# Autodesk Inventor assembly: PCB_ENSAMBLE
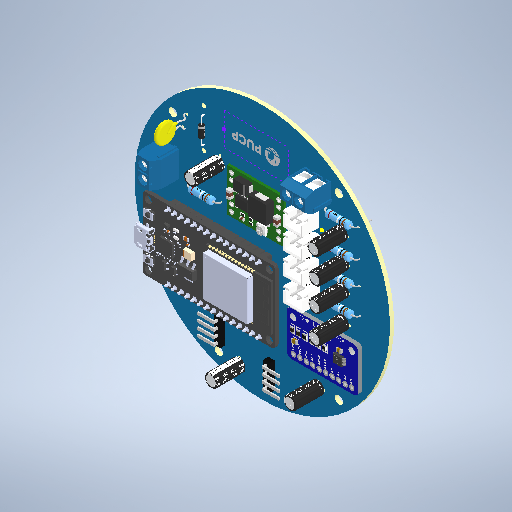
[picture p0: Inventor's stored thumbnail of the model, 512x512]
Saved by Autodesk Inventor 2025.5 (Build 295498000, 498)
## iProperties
Company: Open CASCADE
Created: 2026-10
Part Number: PCB_ENSAMBLE
Description: Designed by EasyEDA Pro
Document SubType Name: Assembly
Designer: Luis M
Authority: Unknown
Sending System: Open CASCADE 7.8
Preprocessor: Open CASCADE STEP processor 7.8
Title: Open CASCADE Shape Model
Author: Author
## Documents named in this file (22)
- C:\Users\Luis M\Desktop\TESIS\CAD_TESIS\PCB\PCB_ENSAMBLE.iam
- C:\Users\Luis M\Downloads\3D_PCB1_2026-10-28\Board~0Dg2.ipt
- C:\Users\Luis M\Downloads\3D_PCB1_2026-10-28\CN1~DL-CONN-JST_XH_2P-P2.50_A2501WV2-2P~XH2.5-2A~pVko.iam
- C:\Users\Luis M\Downloads\3D_PCB1_2026-10-28\CN2~DL-CONN-JST_XH_2P-P2.50_A2501WV2-2P~XH2.5-2A~7OwF.iam
- C:\Users\Luis M\Downloads\3D_PCB1_2026-10-28\CN3~DL-CONN-JST_XH_2P-P2.50_A2501WV2-2P~XH2.5-2A~BYPT.iam
- C:\Users\Luis M\Downloads\3D_PCB1_2026-10-28\CN4~DL-CONN-JST_XH_2P-P2.50_A2501WV2-2P~XH2.5-2A~emIU.iam
- C:\Users\Luis M\Downloads\3D_PCB1_2026-10-28\R1~RES-TH_BD2.7-L8.8-P12.80-D0.5~RES-TH_BD2.7-L8.8-P12.80-D0.5~Nxct.iam
- C:\Users\Luis M\Downloads\3D_PCB1_2026-10-28\R2~RES-TH_BD2.7-L8.8-P12.80-D0.5~RES-TH_BD2.7-L8.8-P12.80-D0.5~5SAl.iam
- C:\Users\Luis M\Downloads\3D_PCB1_2026-10-28\R3~RES-TH_BD2.7-L8.8-P12.80-D0.5~RES-TH_BD2.7-L8.8-P12.80-D0.5~VaNL.iam
- C:\Users\Luis M\Downloads\3D_PCB1_2026-10-28\R4~RES-TH_BD2.7-L8.8-P12.80-D0.5~RES-TH_BD2.7-L8.8-P12.80-D0.5~T5Y4.iam
- C:\Users\Luis M\Downloads\3D_PCB1_2026-10-28\R7~RES-TH_BD2.7-L8.8-P12.80-D0.5~RES-TH_BD2.7-L8.8-P12.80-D0.5~tG5M.iam
- C:\Users\Luis M\Downloads\3D_PCB1_2026-10-28\STEP_DOWN_12V~COMM-SMD_MINI5605V5A~COMM-SMD_MINI5605V5A~D6A4.iam
- C:\Users\Luis M\Downloads\3D_PCB1_2026-10-28\U3~LED-TH_BD4.0-P2.54-FD_RED~LED-TH_BD4.0-P2.54-FD_RED~U7f6.iam
- C:\Users\Luis M\Downloads\3D_PCB1_2026-10-28\ADS1115~ADS1115~16Bit I2C ADC+PGA - ADS1115~8vOy.iam
- C:\Users\Luis M\Downloads\3D_PCB1_2026-10-28\STEP_DOWN_5V~MP1584 STEP DOWN MODULE - PCB~D-SUN_dcdc_step_down_Simple_NoSilk_~2mse.iam
- C:\Users\Luis M\Downloads\3D_PCB1_2026-10-28\U2~ESP32_30P_TH~ESP32-DEVKIT-V1--3DModel-STEP-269445~0cRs.iam
- C:\Users\Luis M\Desktop\TESIS\CAD_TESIS\PCB\bornera.ipt
- C:\Users\Luis M\Desktop\TESIS\CAD_TESIS\PCB\4 pines 90G.iam
- C:\Users\Luis M\Desktop\TESIS\CAD_TESIS\PCB\Pieza50.ipt
- C:\Users\Luis M\Desktop\TESIS\CAD_TESIS\PCB\Elco 10uF-35V (5 x 11 mm).ipt
- C:\Users\Luis M\Desktop\TESIS\CAD_TESIS\PCB\Diode_ 10mm.ipt
- C:\Users\Luis M\Desktop\TESIS\CAD_TESIS\PCB\7.9mm Resettable PTC Radial.ipt
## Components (29 placed, 21 different names)
1. Board~0Dg2_1 — Coincidencia:1, Coincidencia:2, Coincidencia:3
2. CN1 [sub-assembly]
3. CN2 [sub-assembly]
4. CN3 [sub-assembly]
5. CN4 [sub-assembly]
6. R1 [sub-assembly]
7. R2 [sub-assembly]
8. R3 [sub-assembly]
9. R4 [sub-assembly]
10. R7 [sub-assembly]
11. STEP_DOWN_12V [sub-assembly]
12. U3 [sub-assembly]
13. ADS1115 [sub-assembly]
14. STEP_DOWN_5V [sub-assembly]
15. U2 [sub-assembly]
16. bornera:2 — Coincidencia:1, Coincidencia:2, Coincidencia:3
17. bornera:4
18. 4 pines 90G:1 [sub-assembly]
19. 4 pines 90G:2 [sub-assembly]
20. Pieza50:1
21. Elco 10uF-35V (5 x 11 mm):2
22. Elco 10uF-35V (5 x 11 mm):3
23. Elco 10uF-35V (5 x 11 mm):4
24. Elco 10uF-35V (5 x 11 mm):5
25. Elco 10uF-35V (5 x 11 mm):6
26. Elco 10uF-35V (5 x 11 mm):7
27. Elco 10uF-35V (5 x 11 mm):8
28. Diode_ 10mm:1
29. 7.9mm Resettable PTC Radial:1
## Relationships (3: Mate 3)
- Coincidencia:1 [Mate]: Board~0Dg2_1 ↔ bornera:2
- Coincidencia:2 [Mate]: Board~0Dg2_1 ↔ bornera:2
- Coincidencia:3 [Mate]: Board~0Dg2_1 ↔ bornera:2
